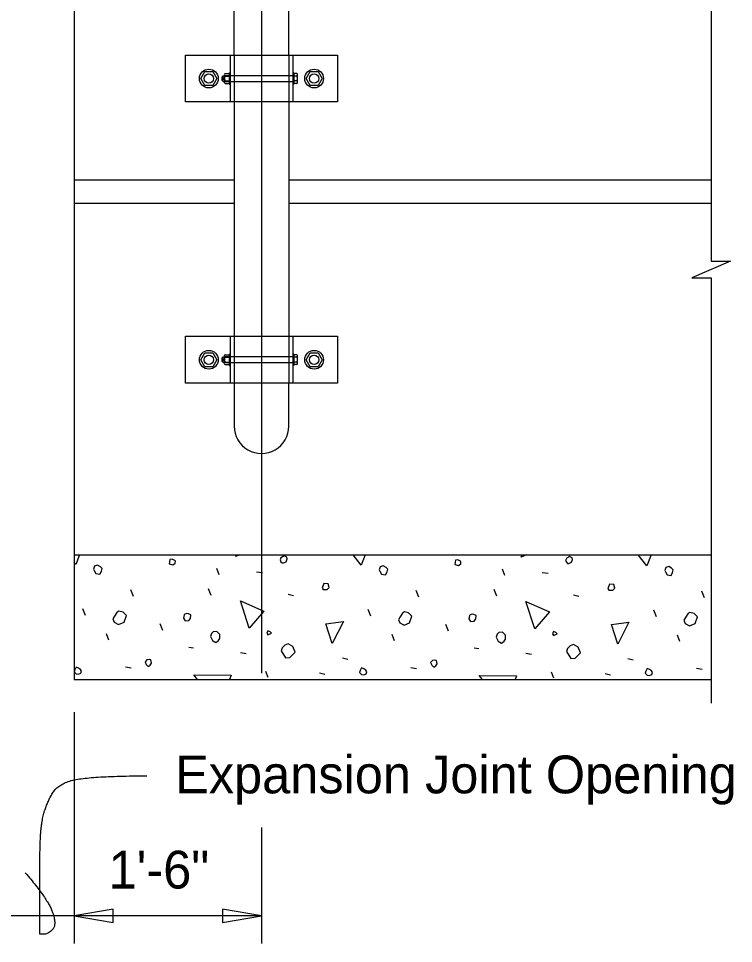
# Model space of a CAD drawing. Extents: x 0 to 72.1, y -7 to 30.
# Drawn here: x 27.295 to 31.111, y 14.116 to 19.05 of the extents above; entities that cross this region are included whole.
import ezdxf

# ---------------------------------------------------------------- set-up
doc = ezdxf.new("R2010")
doc.units = 0
for name, color, linetype in [('AdhocPoint_dp', 7, 'Continuous'), ('Border', 7, 'Continuous'), ('Patterning', 7, 'Continuous'), ('PlotBorder_dp', 7, 'Continuous'), ('SheetBorder_dp', 7, 'Continuous'), ('TextMisc', 7, 'Continuous'), ('TextStructures', 7, 'Continuous')]:
    doc.layers.add(name, color=color, linetype=linetype)

msp = doc.modelspace()

# ---------------------------------------------------------------- linework, layer by layer
at = {"layer": 'AdhocPoint_dp'}
for p, q in [((28.3847, 18.7229), (28.3847, 18.735)), ((28.3904, 18.7229), (28.3904, 18.735)), ((28.3847, 17.2229), (28.3847, 17.235)), ((28.3904, 17.2229), (28.3904, 17.235)), ((29.541, 16.1899), (29.5421, 16.1897)), ((28.3665, 16.0819), (28.3542, 16.1155)), ((28.5663, 16.0978), (28.5981, 16.0943)), ((29.8904, 16.0783), (29.878, 16.1119)), ((30.0901, 16.0943), (30.1219, 16.0907)), ((27.9087, 15.967), (27.8946, 16.0023)), ((28.3241, 15.9723), (28.31, 16.0076)), ((29.4325, 15.9634), (29.4184, 15.9988)), ((29.8479, 15.9687), (29.8338, 16.0041)), ((30.9563, 15.9599), (30.9422, 15.9953)), ((28.7342, 15.9794), (28.7625, 15.9723)), ((30.2581, 15.9758), (30.2863, 15.9687)), ((27.6524, 15.8662), (27.6382, 15.9016)), ((29.1762, 15.8627), (29.162, 15.898)), ((30.7, 15.8591), (30.6859, 15.8945)), ((28.066, 15.7849), (28.0519, 15.8203)), ((29.5898, 15.7814), (29.5757, 15.8167)), ((27.7779, 15.7336), (27.7655, 15.7672)), ((29.3017, 15.7301), (29.2893, 15.7637)), ((30.8255, 15.7266), (30.8131, 15.7601)), ((28.2039, 15.6965), (28.2287, 15.693)), ((29.7277, 15.693), (29.7525, 15.6894)), ((28.4797, 15.6682), (28.5097, 15.6629)), ((30.0035, 15.6647), (30.0336, 15.6594)), ((27.8663, 15.5922), (27.8963, 15.5869)), ((29.0242, 15.6399), (29.0524, 15.6329)), ((30.548, 15.6364), (30.5763, 15.6293)), ((28.6282, 15.5339), (28.6158, 15.5675)), ((28.9022, 15.5604), (28.9305, 15.5533)), ((29.3901, 15.5887), (29.4201, 15.5834)), ((30.152, 15.5303), (30.1396, 15.5639)), ((30.426, 15.5569), (30.4543, 15.5498)), ((30.9139, 15.5851), (30.944, 15.5798))]:
    msp.add_line(p, q, dxfattribs=at)
for points in [[(27.621, 16.1899), (27.6011, 16.1367)], [(28.4549, 16.1809), (28.4577, 16.1899)], [(28.4751, 16.1899), (28.4549, 16.1809)], [(28.7024, 16.1455), (28.7095, 16.1455), (28.7236, 16.1526), (28.7289, 16.1685), (28.7272, 16.1773), (28.713, 16.1844), (28.6954, 16.1738), (28.6918, 16.1632), (28.6954, 16.1526), (28.7024, 16.1455)], [(29.1249, 16.1331), (29.0818, 16.1899)], [(29.1461, 16.1899), (29.1249, 16.1331)], [(29.9788, 16.1773), (29.9826, 16.1899)], [(30.0068, 16.1899), (29.9788, 16.1773)], [(30.6487, 16.1296), (30.6029, 16.1899)], [(30.6713, 16.1899), (30.6487, 16.1296)], [(27.6011, 16.1367), (27.5923, 16.1483)], [(28.0996, 16.1402), (28.1191, 16.1349), (28.1314, 16.1438), (28.1332, 16.1561), (28.1297, 16.1597), (28.1155, 16.1667), (28.1032, 16.165), (28.1014, 16.1526), (28.0996, 16.1402)], [(29.6234, 16.1367), (29.6429, 16.1314), (29.6553, 16.1402), (29.657, 16.1526), (29.6535, 16.1561), (29.6393, 16.1632), (29.627, 16.1614), (29.6252, 16.1491), (29.6234, 16.1367)], [(30.2262, 16.142), (30.2333, 16.142), (30.2475, 16.1491), (30.2528, 16.165), (30.251, 16.1738), (30.2368, 16.1809), (30.2192, 16.1703), (30.2156, 16.1597), (30.2192, 16.1491), (30.2262, 16.142)], [(27.7001, 16.1049), (27.7089, 16.089), (27.7302, 16.0854), (27.739, 16.1013), (27.7425, 16.1155), (27.7337, 16.1243), (27.7178, 16.1331), (27.7019, 16.1278), (27.6966, 16.1119), (27.7001, 16.1049)], [(29.2239, 16.1013), (29.2328, 16.0854), (29.254, 16.0819), (29.2628, 16.0978), (29.2663, 16.1119), (29.2575, 16.1208), (29.2416, 16.1296), (29.2257, 16.1243), (29.2204, 16.1084), (29.2239, 16.1013)], [(30.7477, 16.0978), (30.7566, 16.0819), (30.7778, 16.0783), (30.7866, 16.0943), (30.7902, 16.1084), (30.7813, 16.1172), (30.7654, 16.1261), (30.7495, 16.1208), (30.7442, 16.1049), (30.7477, 16.0978)], [(28.9216, 16.0041), (28.9428, 16.0041), (28.9534, 16.0147), (28.9481, 16.0342), (28.9252, 16.0359), (28.9216, 16.0253), (28.9163, 16.0165), (28.9216, 16.0041), (28.9181, 16.0076)], [(30.4454, 16.0006), (30.4667, 16.0006), (30.4773, 16.0112), (30.472, 16.0306), (30.449, 16.0324), (30.4454, 16.0218), (30.4401, 16.0129), (30.4454, 16.0006), (30.4419, 16.0041)], [(28.5274, 15.7973), (28.4797, 15.944), (28.6052, 15.8892), (28.5274, 15.7973)], [(30.0512, 15.7937), (30.0035, 15.9405), (30.129, 15.8857), (30.0512, 15.7937)], [(27.8062, 15.8291), (27.8291, 15.8167), (27.8592, 15.8291), (27.8716, 15.8662), (27.8539, 15.8839), (27.8309, 15.8892), (27.8203, 15.8821), (27.8079, 15.8627), (27.7991, 15.8468), (27.8062, 15.8291)], [(28.1756, 15.8521), (28.1845, 15.8362), (28.2039, 15.8379), (28.2128, 15.8503), (28.2145, 15.8698), (28.2021, 15.8751), (28.1933, 15.8768), (28.1827, 15.8733), (28.1792, 15.8698), (28.1756, 15.8521)], [(29.33, 15.8256), (29.353, 15.8132), (29.383, 15.8256), (29.3954, 15.8627), (29.3777, 15.8804), (29.3547, 15.8857), (29.3441, 15.8786), (29.3317, 15.8591), (29.3229, 15.8432), (29.33, 15.8256)], [(29.6994, 15.8485), (29.7083, 15.8326), (29.7277, 15.8344), (29.7366, 15.8468), (29.7383, 15.8662), (29.726, 15.8715), (29.7171, 15.8733), (29.7065, 15.8698), (29.703, 15.8662), (29.6994, 15.8485)], [(30.8538, 15.822), (30.8768, 15.8096), (30.9068, 15.822), (30.9192, 15.8591), (30.9015, 15.8768), (30.8785, 15.8821), (30.8679, 15.8751), (30.8556, 15.8556), (30.8467, 15.8397), (30.8538, 15.822)], [(28.9694, 15.716), (28.9358, 15.8203), (29.0295, 15.8326), (28.9694, 15.716)], [(30.4932, 15.7124), (30.4596, 15.8167), (30.5533, 15.8291), (30.4932, 15.7124)], [(28.3206, 15.7531), (28.3312, 15.7319), (28.3489, 15.7213), (28.363, 15.7319), (28.3701, 15.7425), (28.3701, 15.7637), (28.3542, 15.7796), (28.3347, 15.7778), (28.3259, 15.769), (28.3206, 15.7531)], [(28.6264, 15.7619), (28.6459, 15.7708), (28.6388, 15.7778), (28.6264, 15.7831), (28.6211, 15.7708), (28.6264, 15.7619)], [(29.8444, 15.7495), (29.855, 15.7283), (29.8727, 15.7177), (29.8868, 15.7283), (29.8939, 15.7389), (29.8939, 15.7601), (29.878, 15.7761), (29.8585, 15.7743), (29.8497, 15.7655), (29.8444, 15.7495)], [(30.1502, 15.7584), (30.1697, 15.7672), (30.1626, 15.7743), (30.1502, 15.7796), (30.1449, 15.7672), (30.1502, 15.7584)], [(28.6971, 15.6771), (28.7201, 15.6399), (28.7431, 15.6417), (28.7519, 15.6505), (28.7714, 15.67), (28.759, 15.7), (28.7342, 15.7142), (28.7166, 15.7071), (28.7024, 15.693), (28.6971, 15.6771)], [(30.2209, 15.6735), (30.2439, 15.6364), (30.2669, 15.6382), (30.2757, 15.647), (30.2952, 15.6665), (30.2828, 15.6965), (30.2581, 15.7107), (30.2404, 15.7036), (30.2262, 15.6894), (30.2209, 15.6735)], [(27.9776, 15.6046), (27.9882, 15.594), (27.9989, 15.601), (28.0059, 15.6117), (28.0024, 15.6293), (27.9936, 15.6311), (27.9812, 15.6293), (27.9706, 15.6187), (27.9776, 15.6046)], [(29.5015, 15.601), (29.5121, 15.5904), (29.5227, 15.5975), (29.5297, 15.6081), (29.5262, 15.6258), (29.5174, 15.6276), (29.505, 15.6258), (29.4944, 15.6152), (29.5015, 15.601)], [(27.6029, 15.5551), (27.6152, 15.5533), (27.6276, 15.5586), (27.6312, 15.5692), (27.6259, 15.5781), (27.6152, 15.5851), (27.6029, 15.5904), (27.5958, 15.5763), (27.5923, 15.5657), (27.6029, 15.5551)], [(28.2506, 15.5233), (28.2304, 15.5498), (28.4302, 15.548), (28.4209, 15.5233)], [(29.1267, 15.5516), (29.1391, 15.5498), (29.1514, 15.5551), (29.155, 15.5657), (29.1497, 15.5745), (29.1391, 15.5816), (29.1267, 15.5869), (29.1196, 15.5728), (29.1161, 15.5622), (29.1267, 15.5516)], [(29.7717, 15.5233), (29.7542, 15.5462), (29.954, 15.5445), (29.9461, 15.5233)], [(30.6505, 15.548), (30.6629, 15.5462), (30.6753, 15.5516), (30.6788, 15.5622), (30.6735, 15.571), (30.6629, 15.5781), (30.6505, 15.5834), (30.6434, 15.5692), (30.6399, 15.5586), (30.6505, 15.548)]]:
    msp.add_lwpolyline(points, dxfattribs=at)
at = {"layer": 'Border'}
for p, q in [((27.5923, 15.3499), (27.5923, 14.1158)), ((28.5923, 14.2638), (26.2589, 14.2638))]:
    msp.add_line(p, q, dxfattribs=at)
msp.add_lwpolyline([(30.9922, 19.1899), (30.9922, 17.756), (31.0955, 17.756), (30.9922, 17.711), (30.8888, 17.666), (30.9922, 17.666), (30.9922, 15.3986)], dxfattribs=at)
for points in [[(27.5923, 14.2639), (27.8005, 14.2286), (27.8005, 14.2992)], [(28.5923, 14.2639), (28.384, 14.2992), (28.384, 14.2286)]]:
    msp.add_lwpolyline(points, close=True, dxfattribs=at)
msp.add_open_spline([(27.3319, 14.4923), (27.45, 14.356), (27.5015, 14.2167), (27.453, 14.1652), (27.4099, 14.1652), (27.4099, 14.1652), (27.4099, 14.4166), (27.4099, 14.7194), (27.4409, 14.8557), (27.5136, 14.9798), (27.7467, 15.0101), (27.9798, 15.0101)], degree=2, dxfattribs=at)
at = {"layer": 'Patterning'}
for p, q in [((28.4465, 18.8548), (28.4465, 18.6048)), ((28.7381, 18.8548), (28.7381, 18.6048)), ((28.759, 18.7444), (28.3941, 18.7444)), ((28.3941, 18.7145), (28.759, 18.7145)), ((28.4465, 17.3548), (28.4465, 17.1048)), ((28.7381, 17.3548), (28.7381, 17.1048)), ((28.759, 17.2444), (28.3941, 17.2444)), ((28.3941, 17.2145), (28.759, 17.2145))]:
    msp.add_line(p, q, dxfattribs=at)
at = {"layer": 'PlotBorder_dp'}
for p, q in [((28.4465, 18.8548), (28.4465, 19.3307)), ((28.7381, 18.8548), (28.7381, 19.3307)), ((28.1863, 18.8548), (28.9983, 18.8548)), ((28.1863, 18.6048), (28.1863, 18.8548)), ((28.4256, 18.8548), (28.4256, 18.6048)), ((28.759, 18.8548), (28.759, 18.6048)), ((28.9983, 18.8548), (28.9983, 18.6048)), ((28.399, 18.7558), (28.4191, 18.7558)), ((28.4191, 18.7601), (28.4191, 18.6995)), ((28.4191, 18.7601), (28.4256, 18.7601)), ((28.4191, 18.7558), (28.4191, 18.7039)), ((28.7652, 18.7601), (28.7592, 18.7601)), ((28.7652, 18.7601), (28.7652, 18.6995)), ((28.7799, 18.7558), (28.7652, 18.7558)), ((28.3819, 18.7378), (28.3875, 18.7444)), ((28.3819, 18.7201), (28.3819, 18.7378)), ((28.3819, 18.7201), (28.3875, 18.7145)), ((28.3875, 18.7444), (28.3941, 18.7444)), ((28.3875, 18.7145), (28.3875, 18.7444)), ((28.3875, 18.7145), (28.3941, 18.7145)), ((28.3941, 18.7477), (28.3941, 18.712)), ((28.3988, 18.7428), (28.4191, 18.7428)), ((28.3988, 18.7169), (28.4191, 18.7169)), ((28.3991, 18.7039), (28.4191, 18.7039)), ((28.7801, 18.7428), (28.7652, 18.7428)), ((28.7801, 18.7168), (28.7652, 18.7168)), ((28.7799, 18.7038), (28.7652, 18.7038)), ((28.785, 18.7104), (28.785, 18.7493)), ((28.4191, 18.6995), (28.4256, 18.6995)), ((28.7652, 18.6995), (28.7592, 18.6995)), ((28.9983, 18.6048), (28.1863, 18.6048)), ((28.4465, 18.6048), (28.4465, 17.3548)), ((28.7381, 18.6048), (28.7381, 17.3548)), ((28.1863, 17.3548), (28.9983, 17.3548)), ((28.1863, 17.1048), (28.1863, 17.3548)), ((28.4256, 17.3548), (28.4256, 17.1048)), ((28.759, 17.3548), (28.759, 17.1048)), ((28.9983, 17.3548), (28.9983, 17.1048)), ((28.3819, 17.2378), (28.3875, 17.2444)), ((28.3819, 17.2201), (28.3819, 17.2378)), ((28.3875, 17.2444), (28.3941, 17.2444)), ((28.3875, 17.2145), (28.3875, 17.2444)), ((28.3941, 17.2477), (28.3941, 17.212)), ((28.3988, 17.2428), (28.4191, 17.2428)), ((28.399, 17.2558), (28.4191, 17.2558)), ((28.4191, 17.2601), (28.4191, 17.1995)), ((28.4191, 17.2601), (28.4256, 17.2601)), ((28.4191, 17.2558), (28.4191, 17.2039)), ((28.7652, 17.2601), (28.7592, 17.2601)), ((28.7652, 17.2601), (28.7652, 17.1995)), ((28.7799, 17.2558), (28.7652, 17.2558)), ((28.7801, 17.2428), (28.7652, 17.2428)), ((28.785, 17.2104), (28.785, 17.2493)), ((28.3819, 17.2201), (28.3875, 17.2145)), ((28.3875, 17.2145), (28.3941, 17.2145)), ((28.3988, 17.2169), (28.4191, 17.2169)), ((28.3991, 17.2039), (28.4191, 17.2039)), ((28.4191, 17.1995), (28.4256, 17.1995)), ((28.7652, 17.1995), (28.7592, 17.1995)), ((28.7801, 17.2168), (28.7652, 17.2168)), ((28.7799, 17.2038), (28.7652, 17.2038)), ((28.9983, 17.1048), (28.1863, 17.1048)), ((28.4464, 17.1048), (28.4464, 16.8757)), ((28.738, 16.8757), (28.738, 17.1048))]:
    msp.add_line(p, q, dxfattribs=at)
for points in [[(28.2896, 18.7674), (28.333, 18.7674), (28.3547, 18.7298), (28.333, 18.6923), (28.2896, 18.6923), (28.268, 18.7298)], [(28.8516, 18.7674), (28.895, 18.7674), (28.9166, 18.7298), (28.895, 18.6923), (28.8516, 18.6923), (28.8299, 18.7298)], [(28.2896, 17.2674), (28.333, 17.2674), (28.3547, 17.2298), (28.333, 17.1923), (28.2896, 17.1923), (28.268, 17.2298)], [(28.8516, 17.2674), (28.895, 17.2674), (28.9166, 17.2298), (28.895, 17.1923), (28.8516, 17.1923), (28.8299, 17.2298)]]:
    msp.add_lwpolyline(points, close=True, dxfattribs=at)
for centre, radius in [((28.3113, 18.7298), 0.05), ((28.3113, 18.7298), 0.025), ((28.8733, 18.7298), 0.05), ((28.8733, 18.7298), 0.025), ((28.3113, 17.2298), 0.05), ((28.8733, 17.2298), 0.05), ((28.3113, 17.2298), 0.025), ((28.8733, 17.2298), 0.025)]:
    msp.add_circle(centre, radius, dxfattribs=at)
for centre, radius, start, end in [((28.4006, 18.7493), 0.00674, 104.4891, 254.1889), ((28.7783, 18.7493), 0.00673, 285.7823, 75.5404), ((28.4135, 18.7298), 0.0196, 138.628, 221.372), ((28.4006, 18.7104), 0.00673, 105.7823, 255.5404), ((28.7783, 18.7104), 0.00674, 284.4891, 74.1889), ((28.7654, 18.7298), 0.0196, 318.628, 41.372), ((28.4006, 17.2493), 0.00674, 104.4891, 254.1889), ((28.4135, 17.2298), 0.0196, 138.628, 221.372), ((28.7783, 17.2493), 0.00673, 285.7823, 75.5404), ((28.7654, 17.2298), 0.0196, 318.628, 41.372), ((28.4006, 17.2104), 0.00673, 105.7823, 255.5404), ((28.7783, 17.2104), 0.00674, 284.4891, 74.1889)]:
    msp.add_arc(centre, radius, start, end, dxfattribs=at)
msp.add_ellipse((28.5923, 16.8757), major_axis=(0, 0.1458), ratio=0.999499, start_param=1.570796, end_param=4.712389, dxfattribs=at)
at = {"layer": 'SheetBorder_dp'}
for p, q in [((28.5923, 27.5581), (28.5923, 15.5577)), ((28.5923, 14.7353), (28.5923, 14.1158))]:
    msp.add_line(p, q, dxfattribs=at)
at = {"layer": 'TextMisc'}
for p, q in [((27.5923, 19.1899), (27.5923, 15.5233)), ((27.5923, 18.1899), (28.4465, 18.1899)), ((28.7381, 18.1899), (30.9921, 18.1899)), ((27.5923, 18.0649), (28.4465, 18.0649)), ((28.7381, 18.0649), (30.9921, 18.0649)), ((27.5923, 16.1899), (30.9922, 16.1899)), ((27.5923, 15.5233), (30.9922, 15.5233))]:
    msp.add_line(p, q, dxfattribs=at)

# ---------------------------------------------------------------- texts
at = {"layer": 'TextStructures'}
for s, p in [('Expansion Joint Opening', (28.1313, 14.9168)), ('1\'-6"', (27.7765, 14.4091))]:
    msp.add_text(s, height=0.2016, dxfattribs=at).set_placement(p)

doc.saveas('drawing.dxf')
